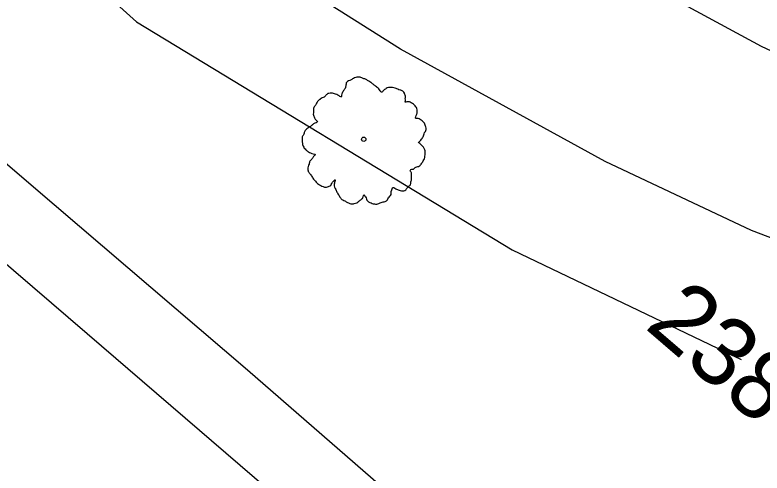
# Model space of a CAD drawing. Extents: x 2076109 to 2080761, y 592812 to 596750.
# Drawn here: x 2077078.6 to 2077165.4, y 596041.6 to 596094.9 of the extents above; entities that cross this region are included whole.
import ezdxf

# ---------------------------------------------------------------- set-up
doc = ezdxf.new("R2010")
doc.units = 0
for name, color, linetype in [('RD_EX_Fence_ChLk', 7, 'Continuous'), ('RD_EX_Misc', 7, 'Continuous'), ('RD_EX_Road', 7, 'Continuous'), ('RD_EX_VEG', 7, 'Continuous'), ('RD_HC_TX_Sta50', 7, 'Continuous')]:
    doc.layers.add(name, color=color, linetype=linetype)

msp = doc.modelspace()

# ---------------------------------------------------------------- linework, layer by layer
at = {"layer": 'RD_EX_Fence_ChLk'}
for points in [[(2076822.972, 596329.732), (2076907.019, 596257.073), (2076948.272, 596221.629), (2077023.379, 596156.571), (2077092.731, 596094.038)], [(2076822.972, 596329.732), (2076907.019, 596257.073), (2076948.272, 596221.629), (2077023.379, 596156.571), (2077092.731, 596094.038)], [(2077092.731, 596094.038), (2077136.391, 596067.523), (2077162.997, 596054.771)], [(2077092.731, 596094.038), (2077136.391, 596067.523), (2077162.997, 596054.771)]]:
    msp.add_lwpolyline(points, dxfattribs=at)
at = {"layer": 'RD_EX_Misc'}
msp.add_lwpolyline([(2076810.466, 596295.642), (2076861.804, 596251.392), (2076900.569, 596218.064), (2076940.756, 596183.48), (2076983.389, 596147.001), (2077038.073, 596099.907), (2077086.972, 596057.778), (2077132.275, 596018.797), (2077181.847, 595976.05), (2077229.693, 595934.908), (2077274.19, 595896.66), (2077329.202, 595849.517), (2077358.599, 595824.219)], dxfattribs=at)
msp.add_lwpolyline([(2076810.466, 596295.642), (2076861.804, 596251.392), (2076900.569, 596218.064), (2076940.756, 596183.48), (2076983.389, 596147.001), (2077038.073, 596099.907), (2077086.972, 596057.778), (2077132.275, 596018.797), (2077181.847, 595976.05), (2077229.693, 595934.908), (2077274.19, 595896.66), (2077329.202, 595849.517), (2077358.599, 595824.219)], dxfattribs=at)
at = {"layer": 'RD_EX_Road'}
for points in [[(2076842.973, 596352.709), (2076866.662, 596333.489), (2076894.557, 596310.647), (2076921.279, 596287.835), (2076946.978, 596265.339), (2076974.88, 596240.878), (2077000.655, 596218.687), (2077026.031, 596196.787), (2077056.62, 596170.549), (2077088.593, 596142.903), (2077102.756, 596132.06), (2077111.621, 596125.076), (2077125.615, 596114.469), (2077137.217, 596107.556), (2077155.374, 596096.638), (2077165.334, 596091.213), (2077183.909, 596082.522), (2077199.736, 596075.752), (2077216.776, 596070.626), (2077234.927, 596066.861), (2077254.139, 596063.854), (2077265.167, 596063.102), (2077275.226, 596063.542), (2077294.176, 596061.91)], [(2076842.973, 596352.709), (2076866.662, 596333.489), (2076894.557, 596310.647), (2076921.279, 596287.835), (2076946.978, 596265.339), (2076974.88, 596240.878), (2077000.655, 596218.687), (2077026.031, 596196.787), (2077056.62, 596170.549), (2077088.593, 596142.903), (2077102.756, 596132.06), (2077111.621, 596125.076), (2077125.615, 596114.469), (2077137.217, 596107.556), (2077155.374, 596096.638), (2077165.334, 596091.213), (2077183.909, 596082.522), (2077199.736, 596075.752), (2077216.776, 596070.626), (2077234.927, 596066.861), (2077254.139, 596063.854), (2077265.167, 596063.102), (2077275.226, 596063.542), (2077294.176, 596061.91)], [(2077310.8, 596045.604), (2077284.614, 596043.933), (2077263.726, 596044.86), (2077236.773, 596048.361), (2077217.912, 596052.268), (2077187.348, 596060.961), (2077164.204, 596069.756), (2077147.202, 596077.801), (2077123.411, 596090.881), (2077107.361, 596101.022), (2077085.709, 596117.864), (2077071.396, 596130.863), (2077033.154, 596164.209), (2077005.119, 596187.538), (2076967.193, 596220.061), (2076925.043, 596258.574), (2076895.709, 596284.714), (2076870.355, 596306.64), (2076830.546, 596340.856)], [(2077310.8, 596045.604), (2077284.614, 596043.933), (2077263.726, 596044.86), (2077236.773, 596048.361), (2077217.912, 596052.268), (2077187.348, 596060.961), (2077164.204, 596069.756), (2077147.202, 596077.801), (2077123.411, 596090.881), (2077107.361, 596101.022), (2077085.709, 596117.864), (2077071.396, 596130.863), (2077033.154, 596164.209), (2077005.119, 596187.538), (2076967.193, 596220.061), (2076925.043, 596258.574), (2076895.709, 596284.714), (2076870.355, 596306.64), (2076830.546, 596340.856)], [(2077309.592, 595877.223), (2077282.743, 595900.374), (2077256.364, 595923.264), (2077227.255, 595948.475), (2077198.785, 595972.866), (2077175.799, 595992.64), (2077153.365, 596012.36), (2077130.636, 596031.731), (2077105.618, 596053.51), (2077080.494, 596075.056), (2077051.539, 596099.906), (2077024.399, 596123.257), (2077002.193, 596142.322), (2076978.911, 596162.671), (2076952.209, 596185.236), (2076929.194, 596204.759), (2076902.686, 596227.389), (2076879.244, 596247.551), (2076859.099, 596264.863), (2076833.455, 596286.99), (2076816.414, 596301.987)], [(2077309.592, 595877.223), (2077282.743, 595900.374), (2077256.364, 595923.264), (2077227.255, 595948.475), (2077198.785, 595972.866), (2077175.799, 595992.64), (2077153.365, 596012.36), (2077130.636, 596031.731), (2077105.618, 596053.51), (2077080.494, 596075.056), (2077051.539, 596099.906), (2077024.399, 596123.257), (2077002.193, 596142.322), (2076978.911, 596162.671), (2076952.209, 596185.236), (2076929.194, 596204.759), (2076902.686, 596227.389), (2076879.244, 596247.551), (2076859.099, 596264.863), (2076833.455, 596286.99), (2076816.414, 596301.987)]]:
    msp.add_lwpolyline(points, dxfattribs=at)
at = {"layer": 'RD_EX_VEG'}
for centre, radius in [((2077119.142, 596080.393), 0.25), ((2077119.142, 596080.393), 0.25), ((2077119.12, 596080.387), 0.0001), ((2077119.12, 596080.387), 0.0001)]:
    msp.add_circle(centre, radius, dxfattribs=at)
for points in [[(2077123.885, 596085.768), (2077123.673, 596085.982), (2077123.361, 596086.116), (2077123.106, 596086.202), (2077122.886, 596086.29), (2077122.65, 596086.36), (2077122.308, 596086.421), (2077122.007, 596086.414), (2077121.75, 596086.305), (2077121.566, 596086.166), (2077121.35, 596085.989), (2077121.237, 596085.855), (2077121.125, 596085.917), (2077121.027, 596086.033), (2077120.886, 596086.252), (2077120.695, 596086.414), (2077120.505, 596086.576), (2077120.222, 596086.784), (2077119.956, 596087.01), (2077119.714, 596087.15), (2077119.434, 596087.323), (2077119.067, 596087.47), (2077118.72, 596087.602), (2077118.33, 596087.605), (2077117.832, 596087.406), (2077117.51, 596087.22), (2077117.234, 596087.127), (2077117.057, 596086.687), (2077116.963, 596086.307), (2077116.853, 596086.139), (2077116.635, 596085.767), (2077116.565, 596085.53), (2077116.531, 596085.297), (2077116.458, 596085.327), (2077116.14, 596085.531), (2077115.846, 596085.65), (2077115.377, 596085.753), (2077115.06, 596085.728), (2077114.773, 596085.545), (2077114.528, 596085.295), (2077114.322, 596085.207), (2077114.087, 596085.046), (2077114.019, 596085.005), (2077113.771, 596084.79), (2077113.556, 596084.383), (2077113.348, 596084.1), (2077113.298, 596083.848), (2077113.299, 596083.617), (2077113.27, 596083.314), (2077113.429, 596082.883), (2077113.612, 596082.597), (2077113.748, 596082.448), (2077113.291, 596082.181), (2077113.026, 596081.947), (2077112.672, 596081.723), (2077112.623, 596081.666), (2077112.278, 596081.336), (2077112.181, 596080.992), (2077111.996, 596080.658), (2077111.983, 596080.373), (2077111.999, 596079.967), (2077112.1, 596079.585), (2077112.4, 596079.166), (2077112.721, 596078.926), (2077113.272, 596078.687), (2077113.511, 596078.582), (2077113.379, 596078.465), (2077113.155, 596078.163), (2077112.88, 596077.84), (2077112.784, 596077.495), (2077112.682, 596077.221), (2077112.634, 596076.933), (2077112.736, 596076.552), (2077112.992, 596076.236), (2077113.219, 596075.846), (2077113.513, 596075.498), (2077113.877, 596075.155), (2077114.431, 596074.881), (2077114.722, 596074.798), (2077114.911, 596074.866), (2077115.306, 596075.022), (2077115.414, 596075.226), (2077115.821, 596075.667), (2077115.784, 596075.469), (2077115.691, 596075.089), (2077115.877, 596074.537), (2077116.069, 596074.144), (2077116.333, 596073.723), (2077116.513, 596073.471), (2077116.923, 596073.221), (2077117.257, 596073.035), (2077117.624, 596072.888), (2077118.03, 596072.903), (2077118.342, 596072.999), (2077118.558, 596073.176), (2077118.858, 596073.413), (2077119.009, 596073.514)], [(2077123.885, 596085.768), (2077123.673, 596085.982), (2077123.361, 596086.116), (2077123.106, 596086.202), (2077122.886, 596086.29), (2077122.65, 596086.36), (2077122.308, 596086.421), (2077122.007, 596086.414), (2077121.75, 596086.305), (2077121.566, 596086.166), (2077121.35, 596085.989), (2077121.237, 596085.855), (2077121.125, 596085.917), (2077121.027, 596086.033), (2077120.886, 596086.252), (2077120.695, 596086.414), (2077120.505, 596086.576), (2077120.222, 596086.784), (2077119.956, 596087.01), (2077119.714, 596087.15), (2077119.434, 596087.323), (2077119.067, 596087.47), (2077118.72, 596087.602), (2077118.33, 596087.605), (2077117.832, 596087.406), (2077117.51, 596087.22), (2077117.234, 596087.127), (2077117.057, 596086.687), (2077116.963, 596086.307), (2077116.853, 596086.139), (2077116.635, 596085.767), (2077116.565, 596085.53), (2077116.531, 596085.297), (2077116.458, 596085.327), (2077116.14, 596085.531), (2077115.846, 596085.65), (2077115.377, 596085.753), (2077115.06, 596085.728), (2077114.773, 596085.545), (2077114.528, 596085.295), (2077114.322, 596085.207), (2077114.087, 596085.046), (2077114.019, 596085.005), (2077113.771, 596084.79), (2077113.556, 596084.383), (2077113.348, 596084.1), (2077113.298, 596083.848), (2077113.299, 596083.617), (2077113.27, 596083.314), (2077113.429, 596082.883), (2077113.612, 596082.597), (2077113.748, 596082.448), (2077113.291, 596082.181), (2077113.026, 596081.947), (2077112.672, 596081.723), (2077112.623, 596081.666), (2077112.278, 596081.336), (2077112.181, 596080.992), (2077111.996, 596080.658), (2077111.983, 596080.373), (2077111.999, 596079.967), (2077112.1, 596079.585), (2077112.4, 596079.166), (2077112.721, 596078.926), (2077113.272, 596078.687), (2077113.511, 596078.582), (2077113.379, 596078.465), (2077113.155, 596078.163), (2077112.88, 596077.84), (2077112.784, 596077.495), (2077112.682, 596077.221), (2077112.634, 596076.933), (2077112.736, 596076.552), (2077112.992, 596076.236), (2077113.219, 596075.846), (2077113.513, 596075.498), (2077113.877, 596075.155), (2077114.431, 596074.881), (2077114.722, 596074.798), (2077114.911, 596074.866), (2077115.306, 596075.022), (2077115.414, 596075.226), (2077115.821, 596075.667), (2077115.784, 596075.469), (2077115.691, 596075.089), (2077115.877, 596074.537), (2077116.069, 596074.144), (2077116.333, 596073.723), (2077116.513, 596073.471), (2077116.923, 596073.221), (2077117.257, 596073.035), (2077117.624, 596072.888), (2077118.03, 596072.903), (2077118.342, 596072.999), (2077118.558, 596073.176), (2077118.858, 596073.413), (2077119.009, 596073.514)], [(2077119.009, 596073.514), (2077119.065, 596073.696), (2077119.189, 596073.918), (2077119.23, 596073.851), (2077119.331, 596073.699), (2077119.46, 596073.426), (2077119.582, 596073.223), (2077119.846, 596073.032), (2077120.12, 596072.93), (2077120.641, 596072.848), (2077121.158, 596073.032), (2077121.626, 596073.158), (2077121.894, 596073.357), (2077122.001, 596073.561), (2077122.306, 596073.958), (2077122.316, 596074.278), (2077122.358, 596074.405), (2077122.541, 596074.775), (2077122.631, 596074.764), (2077122.873, 596074.624), (2077123.239, 596074.477), (2077123.529, 596074.394), (2077123.814, 596074.381), (2077124.017, 596074.504), (2077124.257, 596074.825), (2077124.554, 596075.097), (2077124.594, 596075.26), (2077124.615, 596075.439), (2077124.687, 596075.64), (2077124.67, 596075.851), (2077124.691, 596076.03), (2077124.68, 596076.171), (2077124.682, 596076.366), (2077124.629, 596076.575), (2077124.548, 596076.71), (2077124.607, 596076.856), (2077124.85, 596076.912), (2077124.953, 596076.955), (2077125.118, 596077.111), (2077125.516, 596077.231), (2077125.813, 596077.504), (2077126.05, 596077.86), (2077126.19, 596078.101), (2077126.254, 596078.408), (2077126.263, 596078.728), (2077126.281, 596078.942), (2077126.229, 596079.151), (2077126.063, 596079.456), (2077125.904, 596079.656), (2077125.638, 596079.883), (2077125.518, 596080.05), (2077125.569, 596080.072), (2077125.667, 596080.186), (2077125.845, 596080.396), (2077126.079, 596080.787), (2077126.288, 596081.265), (2077126.305, 596081.284), (2077126.39, 596081.539), (2077126.348, 596081.837), (2077126.28, 596082.027), (2077126.209, 596082.251), (2077126.034, 596082.432), (2077125.806, 596082.626), (2077125.564, 596082.766), (2077125.347, 596082.82), (2077125.133, 596082.838), (2077125.173, 596083.001), (2077125.291, 596083.294), (2077125.35, 596083.44), (2077125.349, 596083.671), (2077125.307, 596083.969), (2077125.045, 596084.355), (2077124.521, 596084.703), (2077124.163, 596084.745), (2077123.936, 596084.709), (2077123.978, 596084.836), (2077123.956, 596085.118), (2077123.993, 596085.316), (2077123.94, 596085.525), (2077123.891, 596085.698), (2077123.847, 596085.801)], [(2077119.009, 596073.514), (2077119.065, 596073.696), (2077119.189, 596073.918), (2077119.23, 596073.851), (2077119.331, 596073.699), (2077119.46, 596073.426), (2077119.582, 596073.223), (2077119.846, 596073.032), (2077120.12, 596072.93), (2077120.641, 596072.848), (2077121.158, 596073.032), (2077121.626, 596073.158), (2077121.894, 596073.357), (2077122.001, 596073.561), (2077122.306, 596073.958), (2077122.316, 596074.278), (2077122.358, 596074.405), (2077122.541, 596074.775), (2077122.631, 596074.764), (2077122.873, 596074.624), (2077123.239, 596074.477), (2077123.529, 596074.394), (2077123.814, 596074.381), (2077124.017, 596074.504), (2077124.257, 596074.825), (2077124.554, 596075.097), (2077124.594, 596075.26), (2077124.615, 596075.439), (2077124.687, 596075.64), (2077124.67, 596075.851), (2077124.691, 596076.03), (2077124.68, 596076.171), (2077124.682, 596076.366), (2077124.629, 596076.575), (2077124.548, 596076.71), (2077124.607, 596076.856), (2077124.85, 596076.912), (2077124.953, 596076.955), (2077125.118, 596077.111), (2077125.516, 596077.231), (2077125.813, 596077.504), (2077126.05, 596077.86), (2077126.19, 596078.101), (2077126.254, 596078.408), (2077126.263, 596078.728), (2077126.281, 596078.942), (2077126.229, 596079.151), (2077126.063, 596079.456), (2077125.904, 596079.656), (2077125.638, 596079.883), (2077125.518, 596080.05), (2077125.569, 596080.072), (2077125.667, 596080.186), (2077125.845, 596080.396), (2077126.079, 596080.787), (2077126.288, 596081.265), (2077126.305, 596081.284), (2077126.39, 596081.539), (2077126.348, 596081.837), (2077126.28, 596082.027), (2077126.209, 596082.251), (2077126.034, 596082.432), (2077125.806, 596082.626), (2077125.564, 596082.766), (2077125.347, 596082.82), (2077125.133, 596082.838), (2077125.173, 596083.001), (2077125.291, 596083.294), (2077125.35, 596083.44), (2077125.349, 596083.671), (2077125.307, 596083.969), (2077125.045, 596084.355), (2077124.521, 596084.703), (2077124.163, 596084.745), (2077123.936, 596084.709), (2077123.978, 596084.836), (2077123.956, 596085.118), (2077123.993, 596085.316), (2077123.94, 596085.525), (2077123.891, 596085.698), (2077123.847, 596085.801)]]:
    msp.add_spline(points, degree=3, dxfattribs=at)

# ---------------------------------------------------------------- texts
at = {"layer": 'RD_HC_TX_Sta50'}
msp.add_text('2380', height=8, rotation=319.29539, dxfattribs=at).set_placement((2077151.656, 596058.504))
msp.add_text('2380', height=8, rotation=319.29539, dxfattribs=at).set_placement((2077151.656, 596058.504))

doc.saveas('drawing.dxf')
